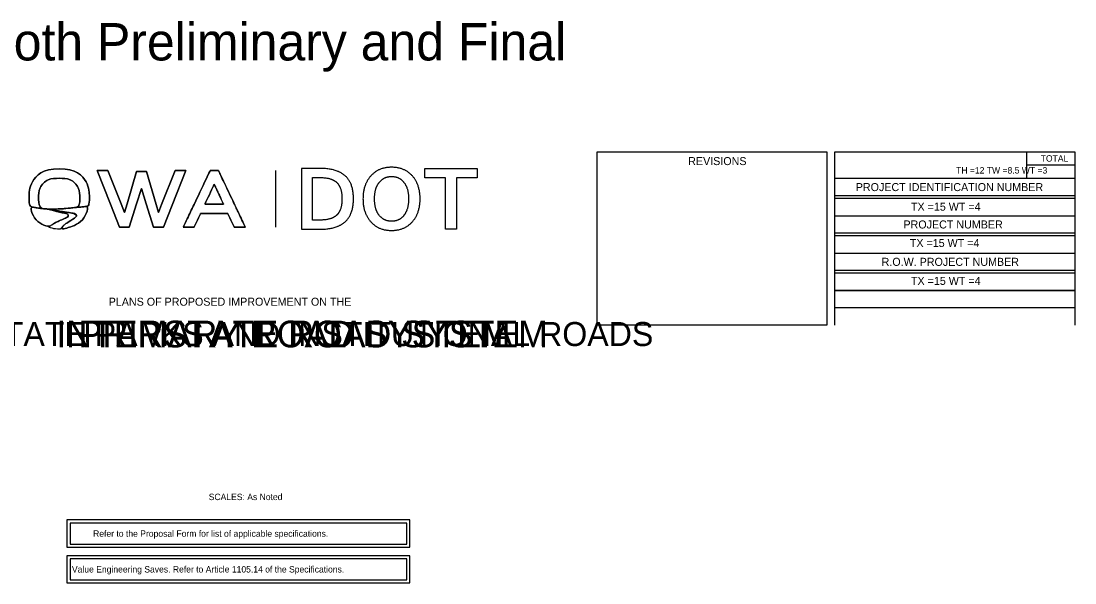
# Model space of a CAD drawing. Extents: x 10196 to 23010, y 6417 to 10189.
# Drawn here: x 11293 to 13268, y 9136 to 10189 of the extents above; entities that cross this region are included whole.
import ezdxf

# ---------------------------------------------------------------- set-up
doc = ezdxf.new("R2010")
doc.units = 0
for name, color, linetype in [('Cell', 7, 'Continuous'), ('Level 1', 7, 'Continuous'), ('Level 11', 7, 'Continuous'), ('Level 5', 7, 'Continuous'), ('Level 6', 7, 'Continuous'), ('Level 61', 7, 'Continuous'), ('Level 7', 7, 'Continuous')]:
    doc.layers.add(name, color=color, linetype=linetype)

msp = doc.modelspace()

# ---------------------------------------------------------------- linework, layer by layer
at = {"layer": 'Cell'}
for p, q in [((11987.1, 9914.9), (11987.1, 9914.9)), ((11460.2, 9846), (11435.4, 9908.6)), ((11435.4, 9908.6), (11436.5, 9908.6)), ((11436.5, 9908.6), (11454.8, 9908.6)), ((11454.8, 9908.6), (11455.3, 9908.6)), ((11455.3, 9908.6), (11480.2, 9846.6)), ((11491.4, 9846.7), (11509.1, 9907.1)), ((11509.1, 9907.1), (11509.6, 9907.1)), ((11509.6, 9907.1), (11527.2, 9907.1)), ((11527.2, 9907.1), (11527.8, 9907.1)), ((11527.8, 9907.1), (11545.8, 9845.5)), ((11556, 9845), (11581.6, 9908.6)), ((11601.4, 9908.6), (11575.7, 9843.8)), ((11581.6, 9908.6), (11582, 9908.6)), ((11582, 9908.6), (11600.3, 9908.6)), ((11600.3, 9908.6), (11601.4, 9908.6)), ((11769.7, 9908.8), (11769.7, 9802.8)), ((11987.1, 9897.7), (11987.1, 9897.7)), ((11518.4, 9875), (11509.4, 9846.6)), ((11527.5, 9846.2), (11518.4, 9875)), ((11477.4, 9802.7), (11460.2, 9846)), ((11480.2, 9846.6), (11486.6, 9830.5)), ((11486.6, 9830.5), (11491.4, 9846.7)), ((11509.4, 9846.6), (11495.5, 9802.7)), ((11541.2, 9802.7), (11527.5, 9846.2)), ((11545.8, 9845.5), (11550.2, 9830.5)), ((11550.2, 9830.5), (11556, 9845)), ((11556, 9845), (11556, 9845)), ((11575.7, 9843.8), (11559.4, 9802.7)), ((11575.7, 9843.8), (11575.7, 9843.8)), ((11477.8, 9802.7), (11477.4, 9802.7)), ((11494.9, 9802.7), (11477.8, 9802.7)), ((11495.5, 9802.7), (11494.9, 9802.7)), ((11541.7, 9802.7), (11541.2, 9802.7)), ((11559, 9802.7), (11541.7, 9802.7)), ((11559.4, 9802.7), (11559, 9802.7))]:
    msp.add_line(p, q, dxfattribs=at)
for points in [[(11601.4, 9908.6), (11600.3, 9908.6), (11582, 9908.6), (11581.6, 9908.6), (11556, 9845), (11556, 9845), (11550.2, 9830.5), (11545.8, 9845.5), (11527.8, 9907.1), (11527.2, 9907.1), (11509.6, 9907.1), (11509.1, 9907.1), (11491.4, 9846.7), (11486.6, 9830.5), (11480.2, 9846.6), (11455.3, 9908.6), (11454.8, 9908.6), (11436.5, 9908.6), (11435.4, 9908.6), (11460.2, 9846), (11477.4, 9802.7), (11477.8, 9802.7), (11494.9, 9802.7), (11495.5, 9802.7), (11509.4, 9846.6), (11518.4, 9875), (11527.5, 9846.2), (11541.2, 9802.7), (11541.7, 9802.7), (11559, 9802.7), (11559.4, 9802.7), (11575.7, 9843.8), (11575.7, 9843.8)], [(12049.1, 9912.9), (12147.3, 9912.9), (12147.3, 9895.3), (12108.6, 9895.3), (12108.6, 9798.7), (12087.8, 9798.7), (12087.8, 9895.3), (12049.1, 9895.3)]]:
    msp.add_lwpolyline(points, close=True, dxfattribs=at)
for points in [[(11851.4, 9912.9), (11818.1, 9912.9), (11818.1, 9798.7), (11851.4, 9798.7)], [(11853.6, 9816.1), (11838.9, 9816.1), (11838.9, 9895.6), (11853.6, 9895.6)]]:
    msp.add_lwpolyline(points, dxfattribs=at)
for points, degree in [([(11987.1, 9914.9), (11962.6, 9914.9), (11948.1, 9898.7)], 2), ([(12026, 9898.7), (12011.5, 9914.9), (11987.1, 9914.9)], 2), ([(11364.3, 9912.1), (11333.1, 9912.1), (11307.8, 9886.8), (11307.8, 9855.6), (11307.8, 9850.7), (11308.5, 9845.9), (11309.7, 9841.3), (11316.3, 9840), (11322.8, 9838.8), (11328.9, 9838), (11329.3, 9838), (11329.7, 9837.9), (11330.1, 9837.9), (11327.3, 9843.2), (11325.7, 9849.2), (11325.7, 9855.6), (11325.7, 9877), (11343, 9894.2), (11364.3, 9894.2), (11385.6, 9894.2), (11402.9, 9877), (11402.9, 9855.6), (11402.9, 9850.1), (11401.7, 9844.8), (11399.5, 9840), (11399.9, 9840), (11400.2, 9840), (11400.6, 9840.1), (11406.7, 9840.7), (11412.9, 9841.4), (11419.1, 9842.2), (11420.1, 9846.5), (11420.8, 9851), (11420.8, 9855.6), (11420.8, 9886.8), (11395.5, 9912.1), (11364.3, 9912.1)], 3), ([(11364.3, 9912.1), (11395.5, 9912.1), (11420.8, 9886.8), (11420.8, 9855.6), (11420.8, 9851), (11420.1, 9846.5), (11419.1, 9842.2), (11412.9, 9841.4), (11406.7, 9840.7), (11400.6, 9840.1), (11400.2, 9840), (11399.9, 9840), (11399.5, 9840), (11401.7, 9844.8), (11402.9, 9850.1), (11402.9, 9855.6), (11402.9, 9877), (11385.6, 9894.2), (11364.3, 9894.2), (11343, 9894.2), (11325.7, 9877), (11325.7, 9855.6), (11325.7, 9849.2), (11327.3, 9843.2), (11330.1, 9837.9), (11329.7, 9837.9), (11329.3, 9838), (11328.9, 9838), (11322.8, 9838.8), (11316.3, 9840), (11309.7, 9841.3), (11308.5, 9845.9), (11307.8, 9850.7), (11307.8, 9855.6), (11307.8, 9886.8), (11333.1, 9912.1), (11364.3, 9912.1)], 3), ([(11346.8, 9836.6), (11363.1, 9836.6), (11381.1, 9838), (11399.5, 9840), (11401.7, 9844.8), (11402.9, 9850.1), (11402.9, 9855.6), (11402.9, 9877), (11385.6, 9894.2), (11364.3, 9894.2), (11343, 9894.2), (11325.7, 9877), (11325.7, 9855.6), (11325.7, 9849.2), (11327.3, 9843.2), (11330.1, 9837.9), (11334.9, 9837.2), (11339.4, 9836.8), (11343.6, 9836.7), (11344.4, 9836.7), (11345.1, 9836.6), (11345.8, 9836.6), (11346.1, 9836.6), (11346.5, 9836.6), (11346.8, 9836.6)], 3), ([(11330.1, 9837.9), (11327.3, 9843.2), (11325.7, 9849.2), (11325.7, 9855.6), (11325.7, 9877), (11343, 9894.2), (11364.3, 9894.2), (11385.6, 9894.2), (11402.9, 9877), (11402.9, 9855.6), (11402.9, 9850.1), (11401.7, 9844.8), (11399.5, 9840)], 3), ([(11699.7, 9830.8), (11699.7, 9830.8), (11662.7, 9908.6), (11662.7, 9908.6), (11662.7, 9908.6), (11647.1, 9908.6), (11647.1, 9908.6), (11647.1, 9908.6), (11614.7, 9840.6), (11614.7, 9840.6), (11614.7, 9840.6), (11596.7, 9802.7), (11596.7, 9802.7), (11596.7, 9802.7), (11617.1, 9802.7), (11617.1, 9802.7), (11617.1, 9802.7), (11629.2, 9828.5), (11629.2, 9828.5), (11629.2, 9828.5), (11680.1, 9828.5), (11680.1, 9828.5), (11680.1, 9828.5), (11692.1, 9802.7), (11692.1, 9802.7), (11692.1, 9802.7), (11713.1, 9802.7), (11713.1, 9802.7), (11713.1, 9802.7), (11699.7, 9830.8), (11699.7, 9830.8)], 3), ([(11662.7, 9908.6), (11662.7, 9908.6), (11647.1, 9908.6), (11647.1, 9908.6), (11647.1, 9908.6), (11614.7, 9840.6), (11614.7, 9840.6), (11614.7, 9840.6), (11596.7, 9802.7), (11596.7, 9802.7), (11596.7, 9802.7), (11617.1, 9802.7), (11617.1, 9802.7), (11617.1, 9802.7), (11629.2, 9828.5), (11629.2, 9828.5), (11629.2, 9828.5), (11680.1, 9828.5), (11680.1, 9828.5), (11680.1, 9828.5), (11692.1, 9802.7), (11692.1, 9802.7), (11692.1, 9802.7), (11713.1, 9802.7), (11713.1, 9802.7), (11713.1, 9802.7), (11699.7, 9830.8), (11699.7, 9830.8)], 3), ([(11699.7, 9830.8), (11699.7, 9830.8), (11662.7, 9908.6), (11662.7, 9908.6)], 2), ([(11900, 9899), (11884.3, 9912.9), (11851.4, 9912.9)], 2), ([(11853.6, 9895.6), (11874.8, 9895.6), (11884.5, 9886.3)], 2), ([(11915.7, 9856), (11915.7, 9885), (11900, 9899)], 2), ([(11948.1, 9898.7), (11933.5, 9882.4), (11933.5, 9855.8)], 2), ([(11963.9, 9886.6), (11972.7, 9897.7), (11987.1, 9897.7)], 2), ([(11987.1, 9897.7), (12001.5, 9897.7), (12010.2, 9886.6)], 2), ([(12040.5, 9855.8), (12040.5, 9882.4), (12026, 9898.7)], 2), ([(11654.7, 9883), (11654.7, 9883), (11672, 9846), (11672, 9846), (11672, 9846), (11637.4, 9846), (11637.4, 9846), (11637.4, 9846), (11654.7, 9883), (11654.7, 9883)], 3), ([(11672, 9846), (11672, 9846), (11637.4, 9846), (11637.4, 9846), (11637.4, 9846), (11654.7, 9883), (11654.7, 9883)], 3), ([(11654.7, 9883), (11654.7, 9883), (11672, 9846), (11672, 9846)], 2), ([(11884.5, 9886.3), (11894.1, 9876.9), (11894.1, 9856)], 2), ([(11955.1, 9855.8), (11955.1, 9875.6), (11963.9, 9886.6)], 2), ([(12010.2, 9886.6), (12018.9, 9875.6), (12018.9, 9855.8)], 2), ([(11894.1, 9856), (11894.1, 9834.8), (11884.5, 9825.4)], 2), ([(11900, 9812.7), (11915.7, 9826.7), (11915.7, 9856)], 2), ([(11933.5, 9855.8), (11933.5, 9829), (11948.1, 9812.8)], 2), ([(11963.9, 9824.9), (11955.1, 9835.9), (11955.1, 9855.8)], 2), ([(12018.9, 9855.8), (12018.9, 9836), (12010.2, 9824.9)], 2), ([(12026, 9812.9), (12040.5, 9829.1), (12040.5, 9855.8)], 2), ([(11364.8, 9831), (11356.5, 9832.8), (11350.1, 9834.4), (11345.6, 9836), (11344.9, 9836.2), (11344.2, 9836.5), (11343.6, 9836.7), (11339.4, 9836.8), (11334.9, 9837.2), (11330.1, 9837.9), (11329.7, 9837.9), (11329.3, 9838), (11328.9, 9838), (11322.8, 9838.8), (11316.3, 9840), (11309.7, 9841.3), (11314.4, 9823.6), (11327.4, 9809.3), (11344.4, 9802.9), (11349.1, 9806.3), (11355.4, 9810.4), (11361.3, 9813.2), (11371.6, 9818.1), (11381.2, 9821.5), (11381.2, 9824.6), (11381.2, 9827.6), (11372.5, 9829.3), (11364.8, 9831)], 3), ([(11364.8, 9831), (11372.5, 9829.3), (11381.2, 9827.6), (11381.2, 9824.6), (11381.2, 9821.5), (11371.6, 9818.1), (11361.3, 9813.2), (11355.4, 9810.4), (11349.1, 9806.3), (11344.4, 9802.9), (11327.4, 9809.3), (11314.4, 9823.6), (11309.7, 9841.3), (11316.3, 9840), (11322.8, 9838.8), (11328.9, 9838), (11329.3, 9838), (11329.7, 9837.9), (11330.1, 9837.9), (11334.9, 9837.2), (11339.4, 9836.8), (11343.6, 9836.7), (11344.2, 9836.5), (11344.9, 9836.2), (11345.6, 9836), (11350.1, 9834.4), (11356.5, 9832.8), (11364.8, 9831)], 3), ([(11343.6, 9836.7), (11343.6, 9836.7), (11343.6, 9836.7), (11343.6, 9836.7), (11339.4, 9836.8), (11334.9, 9837.2), (11330.1, 9837.9)], 3), ([(11345.8, 9836.6), (11345.8, 9836.6), (11345.8, 9836.6), (11345.8, 9836.6), (11345.1, 9836.6), (11344.4, 9836.7), (11343.6, 9836.7)], 3), ([(11385.2, 9829.6), (11375.2, 9831.1), (11369, 9831.9), (11356.9, 9834.2), (11353.7, 9834.9), (11350.9, 9835.4), (11348.4, 9836), (11347.5, 9836.2), (11346.6, 9836.4), (11345.8, 9836.6), (11345.1, 9836.6), (11344.4, 9836.7), (11343.6, 9836.7), (11344.2, 9836.5), (11344.9, 9836.2), (11345.6, 9836), (11350.1, 9834.4), (11356.5, 9832.8), (11364.8, 9831), (11372.5, 9829.3), (11381.2, 9827.6), (11381.2, 9824.6), (11381.2, 9821.5), (11371.6, 9818.1), (11361.3, 9813.2), (11355.4, 9810.4), (11349.1, 9806.3), (11344.4, 9802.9), (11344.6, 9802.8), (11344.7, 9802.7), (11344.9, 9802.7), (11351, 9800.5), (11357.5, 9799.2), (11364.3, 9799.2), (11365.2, 9799.2), (11366.2, 9799.2), (11367.1, 9799.3), (11370.6, 9803.8), (11375.2, 9808.7), (11380.8, 9812.1), (11398.9, 9822.7), (11395.9, 9828), (11385.2, 9829.6)], 3), ([(11399.5, 9840), (11381.1, 9838), (11363.1, 9836.6), (11346.8, 9836.6), (11346.5, 9836.6), (11346.1, 9836.6), (11345.8, 9836.6)], 3), ([(11400.6, 9840.1), (11400.2, 9840), (11399.9, 9840), (11399.5, 9840), (11381.1, 9838), (11363.1, 9836.6), (11346.8, 9836.6), (11346.5, 9836.6), (11346.1, 9836.6), (11345.8, 9836.6), (11346.6, 9836.4), (11347.5, 9836.2), (11348.4, 9836), (11350.9, 9835.4), (11353.7, 9834.9), (11356.9, 9834.2), (11369, 9831.9), (11375.2, 9831.1), (11385.2, 9829.6), (11395.9, 9828), (11398.9, 9822.7), (11380.8, 9812.1), (11375.2, 9808.7), (11370.6, 9803.8), (11367.1, 9799.3), (11372.9, 9799.6), (11378.5, 9800.8), (11383.7, 9802.7), (11401.2, 9809.1), (11414.6, 9823.8), (11419.1, 9842.2), (11412.9, 9841.4), (11406.7, 9840.7), (11400.6, 9840.1)], 3), ([(11400.6, 9840.1), (11406.7, 9840.7), (11412.9, 9841.4), (11419.1, 9842.2), (11414.6, 9823.8), (11401.2, 9809.1), (11383.7, 9802.7), (11378.5, 9800.8), (11372.9, 9799.6), (11367.1, 9799.3), (11370.6, 9803.8), (11375.2, 9808.7), (11380.8, 9812.1), (11398.9, 9822.7), (11395.9, 9828), (11385.2, 9829.6), (11375.2, 9831.1), (11369, 9831.9), (11356.9, 9834.2), (11353.7, 9834.9), (11350.9, 9835.4), (11348.4, 9836), (11347.5, 9836.2), (11346.6, 9836.4), (11345.8, 9836.6), (11346.1, 9836.6), (11346.5, 9836.6), (11346.8, 9836.6), (11363.1, 9836.6), (11381.1, 9838), (11399.5, 9840), (11399.9, 9840), (11400.2, 9840), (11400.6, 9840.1)], 3), ([(11884.5, 9825.4), (11874.8, 9816.1), (11853.6, 9816.1)], 2), ([(11987.1, 9813.8), (11972.7, 9813.8), (11963.9, 9824.9)], 2), ([(12010.2, 9824.9), (12001.5, 9813.8), (11987.1, 9813.8)], 2), ([(11851.4, 9798.7), (11884.2, 9798.7), (11900, 9812.7)], 2), ([(11948.1, 9812.8), (11962.6, 9796.6), (11987.1, 9796.6)], 2), ([(11987.1, 9796.6), (12011.5, 9796.6), (12026, 9812.9)], 2)]:
    msp.add_open_spline(points, degree=degree, dxfattribs=at)
at = {"layer": 'Level 1'}
for p, q in [((12817.5, 9684), (12817.5, 9944)), ((12817.5, 9944), (13267.5, 9944)), ((12817.5, 9944), (13267.5, 9944)), ((13177.5, 9894), (13177.5, 9944)), ((13177.5, 9894), (13177.5, 9944)), ((13267.5, 9944), (13267.5, 9684)), ((13267.5, 9944), (13267.5, 9619)), ((13267.5, 9919), (13177.5, 9919)), ((13177.5, 9919), (13177.5, 9919)), ((13267.5, 9919), (13177.5, 9919)), ((13177.5, 9919), (13177.5, 9919)), ((12817.5, 9894), (12817.5, 9894)), ((12817.5, 9894), (12817.5, 9894)), ((12817.5, 9619), (12817.5, 9894)), ((13267.5, 9894), (12817.5, 9894)), ((13267.5, 9861.5), (12817.5, 9861.5)), ((13267.5, 9861.5), (12817.5, 9861.5)), ((13267.5, 9856.5), (12817.5, 9856.5)), ((13267.5, 9856.5), (12817.5, 9856.5)), ((12817.5, 9824), (13267.5, 9824)), ((12817.5, 9824), (13267.5, 9824)), ((13267.5, 9791.5), (12817.5, 9791.5)), ((13267.5, 9791.5), (12817.5, 9791.5)), ((13267.5, 9786.5), (12817.5, 9786.5)), ((13267.5, 9786.5), (12817.5, 9786.5)), ((12817.5, 9754), (13267.5, 9754)), ((12817.5, 9754), (13267.5, 9754)), ((13267.5, 9721.5), (12817.5, 9721.5)), ((13267.5, 9721.5), (12817.5, 9721.5)), ((13267.5, 9716.5), (12817.5, 9716.5)), ((13267.5, 9716.5), (12817.5, 9716.5)), ((12817.5, 9684), (13267.5, 9684)), ((13267.5, 9684), (12817.5, 9684)), ((13267.5, 9651.5), (12817.5, 9651.5))]:
    msp.add_line(p, q, dxfattribs=at)
msp.add_lwpolyline([(12372.5, 9619), (12372.5, 9944), (12802.5, 9944), (12802.5, 9619), (12372.5, 9619)], dxfattribs=at)
for points in [[(11378.7, 9203.4), (12021.3, 9203.4), (12021.3, 9254.3), (11378.7, 9254.3)], [(11384.5, 9209.2), (12015.5, 9209.2), (12015.5, 9248.4), (11384.5, 9248.4)]]:
    msp.add_lwpolyline(points, close=True, dxfattribs=at)
at = {"layer": 'Level 11'}
for points in [[(11378.7, 9136.4), (12021.3, 9136.4), (12021.3, 9187.4), (11378.7, 9187.4)], [(11384.5, 9142.3), (12015.5, 9142.3), (12015.5, 9181.5), (11384.5, 9181.5)]]:
    msp.add_lwpolyline(points, close=True, dxfattribs=at)

# ---------------------------------------------------------------- texts
at = {"layer": 'Level 1'}
for s, height, p in [('Title Sheet, both Preliminary and Final', 70, (10727.4, 10115)), ('REVISIONS', 15, (12542.9, 9919)), ('TOTAL', 12, (13203.4, 9925.5)), ('PROJECT IDENTIFICATION NUMBER', 15, (12856.9, 9870.3)), ('PROJECT NUMBER', 15, (12946.2, 9800.3)), ('R.O.W. PROJECT NUMBER', 15, (12905.3, 9730.3)), ('PLANS OF PROPOSED IMPROVEMENT ON THE', 15, (11457, 9655.6)), ('SCALES: As Noted', 12, (11644.4, 9291.5)), ('Refer to the Proposal Form for list of applicable specifications.', 12, (11427.8, 9222.8))]:
    msp.add_text(s, height=height, dxfattribs=at).set_placement(p)
at = {"layer": 'Level 11'}
msp.add_text('Value Engineering Saves. Refer to Article 1105.14 of the Specifications.', height=12, dxfattribs=at).set_placement((11388.1, 9155.9))
at = {"layer": 'Level 5'}
msp.add_text('PRIMARY ROAD SYSTEM', height=50, dxfattribs=at).set_placement((11400.5, 9577.6))
at = {"layer": 'Level 6'}
msp.add_text('INTERSTATE ROAD SYSTEM', height=50, dxfattribs=at).set_placement((11358.7, 9577.6))
at = {"layer": 'Level 61'}
for s, height, p in [('TH =12 TW =8.5 WT =3', 12, (13044.9, 9903.2)), ('TX =15 WT =4', 15, (12960.3, 9833.6)), ('TX =15 WT =4', 15, (12958.2, 9765.6)), ('TX =15 WT =4', 15, (12960.3, 9694.6))]:
    msp.add_text(s, height=height, dxfattribs=at).set_placement(p)
at = {"layer": 'Level 7'}
msp.add_text('STATE PARKS AND INSTITUTIONAL ROADS', height=45, dxfattribs=at).set_placement((11220.3, 9580.1))

doc.saveas('drawing.dxf')
